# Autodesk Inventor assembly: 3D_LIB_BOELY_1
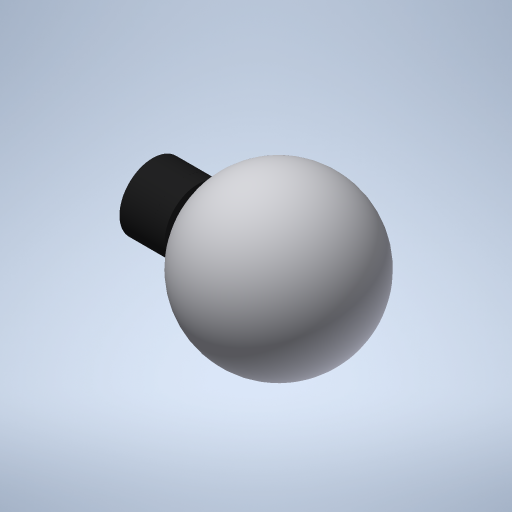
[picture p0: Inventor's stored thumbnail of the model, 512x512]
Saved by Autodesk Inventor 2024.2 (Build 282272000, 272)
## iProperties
Created: 2023-11
Part Number: 3D_LIB_BOELY_1
Project: 452 - BOELY
Description: BOELY Wall - Assy
Document SubType Name: Assembly
Designer: Manuel
Manager: Filip
Company: DARK
Author: Manuel
Revision Number: v0
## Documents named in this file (8)
- C:\Users\Stage\Desktop\Stage Karsten\armatures\452 - BOELY\3D_LIB_BOELY_1.iam
- C:\Users\Stage\Desktop\Stage Karsten\armatures\452 - BOELY\379-057.ipt
- N:\LIBRARY\FITTINGEN\BJB 25.834_G9.ipt
- N:\LIBRARY\FITTINGEN\BJB 25.934_for G9.ipt
- N:\LIBRARY\BEVESTIGING\Draadstang-trompetnipple\Draadstang M10x1 L16.ipt
- C:\Users\Stage\Desktop\Stage Karsten\armatures\452 - BOELY\452-001.ipt
- C:\Users\Stage\Desktop\Stage Karsten\armatures\452 - BOELY\Glass Sphere Dia.100mm.ipt
- N:\LIBRARY\LAMPEN\LED\G9-6W-2700K-CRI 90.ipt
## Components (7 placed, 7 different names)
1. 379-057:1 — Mate:7, Mate:8, Angle:2, Mate:11, Mate:18, Flush:1, Mate:19
2. BJB 25.834_G9:1 — Mate:5, Mate:6, Angle:3, Mate:14, Mate:15, Mate:17
3. BJB 25.934_for G9:1 — Angle:1, Mate:3, Mate:4, Mate:5, Mate:6, Mate:9, Mate:10, Mate:17
4. Draadstang M10x1 L16:1 — Angle:1, Mate:3, Mate:4
5. 452-001:1 — Mate:7, Mate:8, Mate:9, Mate:10, Mate:12
6. Glass Sphere Dia.100mm:1 — Angle:2, Mate:11, Mate:12
7. G9-6W-2700K-CRI 90:1 — Angle:3, Mate:14, Mate:15
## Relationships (19: Mate 15, Angle 3, Flush 1)
- Angle:1: BJB 25.934_for G9:1 ↔ Draadstang M10x1 L16:1
- Mate:3: BJB 25.934_for G9:1 ↔ Draadstang M10x1 L16:1
- Mate:4: BJB 25.934_for G9:1 ↔ Draadstang M10x1 L16:1
- Mate:5: BJB 25.834_G9:1 ↔ BJB 25.934_for G9:1
- Mate:6: BJB 25.834_G9:1 ↔ BJB 25.934_for G9:1
- Mate:7: 379-057:1 ↔ 452-001:1
- Mate:8: 379-057:1 ↔ 452-001:1
- Mate:9: BJB 25.934_for G9:1 ↔ 452-001:1
- Mate:10: BJB 25.934_for G9:1 ↔ 452-001:1
- Angle:2: 379-057:1 ↔ Glass Sphere Dia.100mm:1
- Mate:11: 379-057:1 ↔ Glass Sphere Dia.100mm:1
- Mate:12: 452-001:1 ↔ Glass Sphere Dia.100mm:1
- Angle:3: BJB 25.834_G9:1 ↔ G9-6W-2700K-CRI 90:1
- Mate:14: BJB 25.834_G9:1 ↔ G9-6W-2700K-CRI 90:1
- Mate:15: BJB 25.834_G9:1 ↔ G9-6W-2700K-CRI 90:1
- Mate:17: BJB 25.834_G9:1 ↔ BJB 25.934_for G9:1
- Mate:18: 379-057:1
- Flush:1: 379-057:1
- Mate:19: 379-057:1
